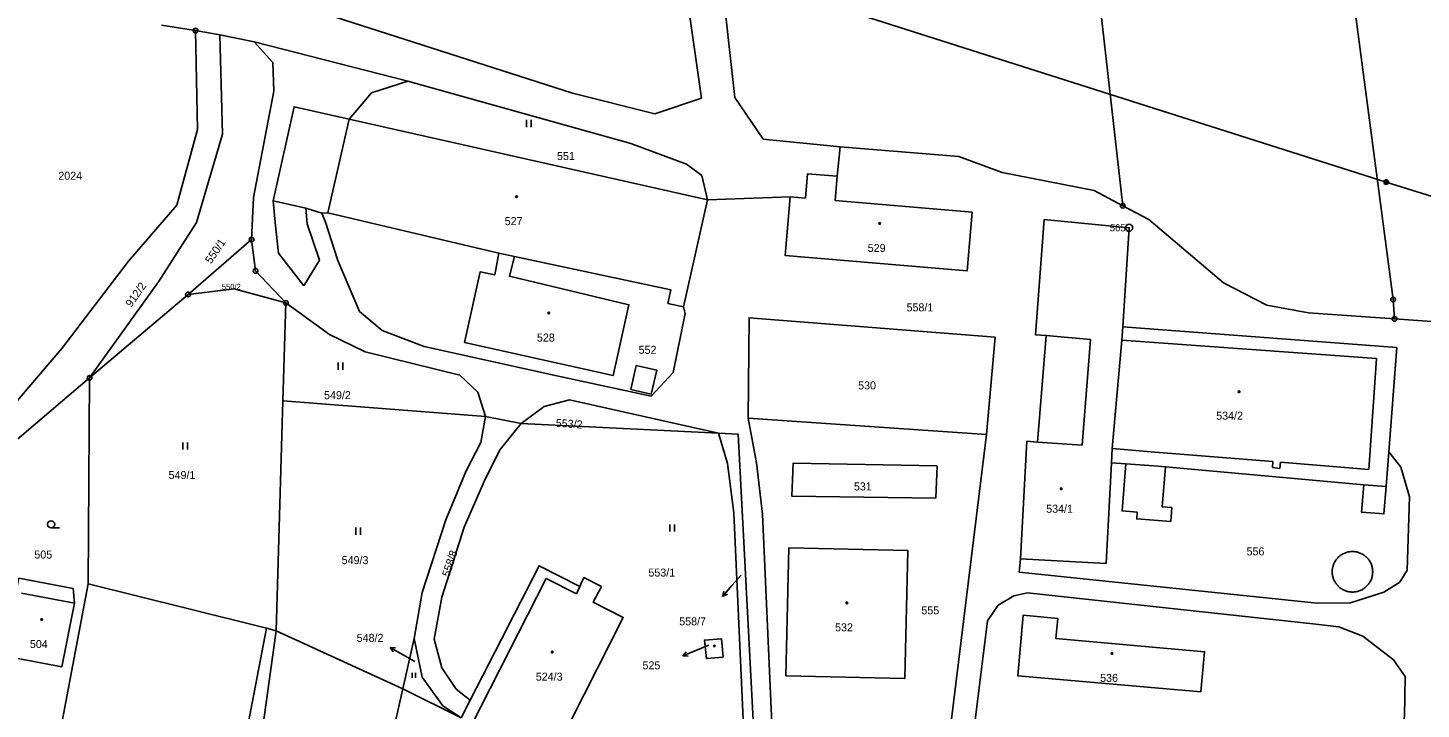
# Model space of a CAD drawing. Extents: x -504988 to -494607, y -1123820 to -1114018.
# Drawn here: x -499771.3 to -499475.3, y -1121291.8 to -1121147.2 of the extents above; entities that cross this region are included whole.
import ezdxf

# ---------------------------------------------------------------- set-up
doc = ezdxf.new("R2010")
doc.units = 0
for name, color, linetype in [('Hranice parcel', 7, 'Continuous'), ('Parcelní čísla', 7, 'Continuous'), ('Pop  PČ popisy', 7, 'Continuous'), ('Poz předměty', 7, 'Continuous'), ('Vnitřní kresba', 7, 'Continuous'), ('Značky bodu BP', 7, 'Continuous'), ('Značky budov', 7, 'Continuous'), ('Značky kultur', 7, 'Continuous')]:
    doc.layers.add(name, color=color, linetype=linetype)

msp = doc.modelspace()

# ---------------------------------------------------------------- linework, layer by layer
at = {"layer": 'Hranice parcel'}
for p, q in [((-499742.85, -1121146.58), (-499735.62, -1121147.76)), ((-499730.48, -1121148.62), (-499735.62, -1121147.76)), ((-499723.21, -1121150.1), (-499730.48, -1121148.62)), ((-499723.21, -1121150.1), (-499690.55, -1121158.46)), ((-499626.88, -1121183.66), (-499703.04, -1121166.56)), ((-499599.32, -1121178.67), (-499598.7, -1121172.43)), ((-499626.88, -1121183.66), (-499609.35, -1121183.04)), ((-499632, -1121206.43), (-499626.88, -1121183.66)), ((-499737.24, -1121203.77), (-499723.72, -1121192.13)), ((-499671.18, -1121195.02), (-499667.9, -1121195.75)), ((-499758.14, -1121221.5), (-499737.24, -1121203.77)), ((-499717.12, -1121226.36), (-499716.43, -1121205.57)), ((-499499.24, -1121207.68), (-499480.94, -1121208.98)), ((-499758.14, -1121221.5), (-499774.43, -1121235.32)), ((-499758.14, -1121221.5), (-499758.45, -1121265.23)), ((-499718.5, -1121275.17), (-499717.12, -1121226.36)), ((-499717.12, -1121226.36), (-499674.05, -1121229.68)), ((-499666.49, -1121231.16), (-499674.05, -1121229.68)), ((-499618.28, -1121230.05), (-499567.62, -1121233.51)), ((-499624.55, -1121233.22), (-499666.49, -1121231.16)), ((-499724.89, -1121297.16), (-499720.54, -1121274.67)), ((-499718.5, -1121275.17), (-499720.54, -1121274.67)), ((-499718.5, -1121275.17), (-499691.64, -1121287.55)), ((-499689.23, -1121276.84), (-499691.64, -1121287.55)), ((-499679.21, -1121293.69), (-499691.64, -1121287.55)), ((-499679.21, -1121293.69), (-499677.32, -1121289.95))]:
    msp.add_line(p, q, dxfattribs=at)
for points in [[(-499722.3, -1121143.47), (-499711.61, -1121143.06), (-499655.54, -1121161.04), (-499638.1, -1121165.41), (-499628.17, -1121162.11), (-499636.17, -1121106.02), (-499642.87, -1121066.62), (-499646.88, -1121045.2)], [(-499598.7, -1121172.43), (-499615.06, -1121170.79), (-499621.06, -1121161.96), (-499627.39, -1121105.08), (-499634.8, -1121065.28), (-499638.31, -1121046.8)], [(-499554.62, -1121062.41), (-499546.23, -1121118.09), (-499538.66, -1121184.94)], [(-499480.94, -1121208.98), (-499481.24, -1121204.85), (-499489.09, -1121145.31), (-499501.25, -1121074.72), (-499501.77, -1121072.27)], [(-499735.62, -1121147.76), (-499735.23, -1121168.72), (-499739.59, -1121184.85), (-499749.86, -1121196.74), (-499764.05, -1121215.27), (-499775.18, -1121228.26)], [(-499730.48, -1121148.62), (-499729.89, -1121169.75), (-499735.45, -1121188.47), (-499743.52, -1121201.09), (-499758.14, -1121221.5)], [(-499723.72, -1121192.13), (-499723.33, -1121183.19), (-499719.03, -1121160.6), (-499719.22, -1121154.49), (-499723.21, -1121150.1)], [(-499690.55, -1121158.46), (-499698.25, -1121160.95), (-499703.04, -1121166.56)], [(-499626.88, -1121183.66), (-499628.06, -1121178.54), (-499631.38, -1121176.11), (-499643.16, -1121171.74), (-499690.55, -1121158.46)], [(-499703.04, -1121166.56), (-499714.7, -1121163.91), (-499719.17, -1121183.93), (-499712.22, -1121185.47), (-499708.81, -1121186.5)], [(-499598.7, -1121172.43), (-499573.53, -1121174.51), (-499564.31, -1121177.87), (-499544.74, -1121181.71), (-499538.66, -1121184.94)], [(-499609.35, -1121183.04), (-499610.4, -1121195.48), (-499571.72, -1121198.74), (-499570.67, -1121186.3), (-499599.76, -1121183.85), (-499599.32, -1121178.67)], [(-499599.32, -1121178.67), (-499605.64, -1121178.14), (-499606.07, -1121183.32), (-499609.35, -1121183.04)], [(-499538.66, -1121184.94), (-499533.11, -1121187.89), (-499517.28, -1121201.31), (-499508.05, -1121206.07), (-499499.24, -1121207.68)], [(-499708.81, -1121186.5), (-499707.51, -1121186.46), (-499671.18, -1121195.02)], [(-499708.81, -1121186.5), (-499708.06, -1121188.46), (-499705.38, -1121196.55), (-499700.82, -1121207.36), (-499695.99, -1121211.43), (-499687.05, -1121214.82), (-499658.23, -1121221.22), (-499638.82, -1121225.39), (-499634.15, -1121220.36), (-499631.66, -1121207.8), (-499632, -1121206.43)], [(-499560.39, -1121259.88), (-499559.03, -1121234.96), (-499556.77, -1121235.15), (-499554.95, -1121212.51), (-499557.18, -1121212.37), (-499555.34, -1121187.89), (-499537.33, -1121189.62), (-499538.68, -1121210.68)], [(-499716.43, -1121205.57), (-499722.89, -1121198.76), (-499723.72, -1121192.13)], [(-499671.18, -1121195.02), (-499672.08, -1121199.63), (-499675.15, -1121198.95), (-499678.49, -1121213.98), (-499646.92, -1121221), (-499643.57, -1121205.97), (-499668.97, -1121199.92), (-499667.9, -1121195.75)], [(-499667.9, -1121195.75), (-499634.67, -1121202.81), (-499635.31, -1121205.68), (-499632, -1121206.43)], [(-499737.24, -1121203.77), (-499727.4, -1121202.59), (-499716.43, -1121205.57)], [(-499674.05, -1121229.68), (-499675.68, -1121224.55), (-499679.53, -1121220.94), (-499699.59, -1121215.95), (-499707.18, -1121212.31), (-499716.43, -1121205.57)], [(-499567.62, -1121233.51), (-499565.81, -1121212.87), (-499618.07, -1121208.74), (-499618.28, -1121230.05)], [(-499480.94, -1121208.98), (-499472, -1121209.62), (-499440.51, -1121211.63)], [(-499541.06, -1121239.56), (-499540.89, -1121236.51), (-499538.86, -1121213.5), (-499538.68, -1121210.68)], [(-499482.15, -1121237.17), (-499480.49, -1121215.04), (-499538.68, -1121210.68)], [(-499624.55, -1121233.22), (-499656.21, -1121226.16), (-499661.56, -1121227.54), (-499666.49, -1121231.16)], [(-499674.05, -1121229.68), (-499675.04, -1121235.19), (-499678.16, -1121241.24), (-499682.49, -1121251.62), (-499687.51, -1121267.04), (-499689.23, -1121276.84)], [(-499618.28, -1121230.05), (-499616.51, -1121239.55), (-499615.21, -1121250.4), (-499612.69, -1121306), (-499607.63, -1121311.95), (-499585.22, -1121315.4), (-499580.65, -1121312.61), (-499576.84, -1121308.33), (-499567.62, -1121233.51)], [(-499666.49, -1121231.16), (-499670.9, -1121236.72), (-499674.14, -1121242.98), (-499678.55, -1121253.22), (-499683.33, -1121268.05), (-499684.97, -1121276.97), (-499683.34, -1121283.06), (-499680.26, -1121287.6), (-499677.32, -1121289.95)], [(-499627.36, -1121310.43), (-499621.98, -1121308.54), (-499618.81, -1121305.01), (-499621.32, -1121250.12), (-499622.64, -1121239.66), (-499624.55, -1121233.22)], [(-499624.55, -1121233.22), (-499620.4, -1121233.46), (-499616.25, -1121311.73)], [(-499560.39, -1121259.88), (-499560.71, -1121262.72), (-499497.4, -1121269.35), (-499490.27, -1121269.24), (-499483.23, -1121266.97), (-499479.82, -1121264.88), (-499478.23, -1121262.3), (-499477.76, -1121246.78), (-499479.63, -1121240.44), (-499482.15, -1121237.17)], [(-499541.06, -1121239.56), (-499538.01, -1121239.75), (-499538.82, -1121249.75), (-499535.58, -1121250.01), (-499535.69, -1121251.43), (-499528.49, -1121251.97), (-499528.26, -1121249.02), (-499530.28, -1121248.86), (-499529.59, -1121240.39), (-499487.5, -1121244.17), (-499487.99, -1121249.98), (-499483.21, -1121250.36), (-499482.71, -1121244.54), (-499482.15, -1121237.17)], [(-499578.35, -1121247.06), (-499578.12, -1121240.17), (-499608.66, -1121239.58), (-499608.96, -1121246.61), (-499578.35, -1121247.06)], [(-499560.39, -1121259.88), (-499542.22, -1121260.9), (-499541.06, -1121239.56)], [(-499584.96, -1121285.36), (-499584.3, -1121258.17), (-499609.59, -1121257.57), (-499610.24, -1121284.75), (-499584.96, -1121285.36)], [(-499658.64, -1121299.61), (-499644.8, -1121272.34), (-499651.14, -1121269.15), (-499649.42, -1121265.81), (-499653.19, -1121263.9), (-499654, -1121265.77), (-499662.66, -1121261.39), (-499677.32, -1121289.95)], [(-499775.2, -1121280.69), (-499764.01, -1121282.84), (-499761.38, -1121269.32), (-499761.6, -1121266.24), (-499773.15, -1121264.04), (-499776.76, -1121280.41), (-499775.2, -1121280.69)], [(-499768.83, -1121319.89), (-499768.42, -1121317.94), (-499758.45, -1121265.23)], [(-499720.54, -1121274.67), (-499737.38, -1121270.46), (-499758.45, -1121265.23)], [(-499486.87, -1121324.22), (-499486.86, -1121323.39), (-499479.81, -1121298.97), (-499478.82, -1121293.36), (-499478.67, -1121284.88), (-499481.16, -1121281.36), (-499487.7, -1121276.33), (-499492.76, -1121274.33), (-499497.63, -1121273.78), (-499558.94, -1121267.14), (-499561.8, -1121267.75), (-499565.13, -1121269.75), (-499567.38, -1121273.1), (-499570.95, -1121301.52)], [(-499522.06, -1121288.16), (-499521.31, -1121279.63), (-499552.88, -1121276.86), (-499552.5, -1121272.55), (-499559.85, -1121271.9), (-499560.97, -1121284.74), (-499522.06, -1121288.16)], [(-499721.37, -1121318.52), (-499723.64, -1121312.8), (-499722.48, -1121303.72), (-499718.5, -1121275.17)], [(-499689.23, -1121276.84), (-499687.48, -1121285.03), (-499683.09, -1121291.14), (-499679.21, -1121293.69)], [(-499623.91, -1121276.89), (-499627.53, -1121277.15), (-499627.13, -1121281.11), (-499623.58, -1121280.82), (-499623.91, -1121276.89)], [(-499691.64, -1121287.55), (-499697.61, -1121314.02), (-499705.71, -1121331.61)]]:
    msp.add_lwpolyline(points, dxfattribs=at)
at = {"layer": 'Pop  PČ popisy'}
for p, q in [((-499621.72, -1121265.61), (-499623.69, -1121267.88)), ((-499619.75, -1121263.36), (-499621.72, -1121265.61)), ((-499623.69, -1121267.88), (-499623.41, -1121266.79)), ((-499623.69, -1121267.88), (-499622.65, -1121267.45)), ((-499691.68, -1121280.23), (-499694.28, -1121278.73)), ((-499694.28, -1121278.73), (-499693.16, -1121278.8)), ((-499694.28, -1121278.73), (-499693.66, -1121279.66)), ((-499689.09, -1121281.74), (-499691.68, -1121280.23)), ((-499629.35, -1121279.39), (-499632.13, -1121280.51)), ((-499632.13, -1121280.51), (-499631.39, -1121279.68)), ((-499632.13, -1121280.51), (-499631.02, -1121280.6)), ((-499626.57, -1121278.27), (-499629.35, -1121279.39))]:
    msp.add_line(p, q, dxfattribs=at)
at = {"layer": 'Poz předměty'}
for p, q in [((-499632.39, -1121132.32), (-499482.71, -1121179.91)), ((-499482.71, -1121179.91), (-499339.41, -1121225.24))]:
    msp.add_line(p, q, dxfattribs=at)
for radius in [0.5, 0.4, 0.3, 0.2, 0.1]:
    msp.add_circle((-499482.71, -1121179.91), radius, dxfattribs=at)
at = {"layer": 'Vnitřní kresba'}
for p, q in [((-499707.51, -1121186.46), (-499703.04, -1121166.56)), ((-499718.66, -1121189.23), (-499719.17, -1121183.93)), ((-499712.22, -1121185.47), (-499711.96, -1121188.78)), ((-499711.96, -1121188.78), (-499709.32, -1121196.51)), ((-499718.04, -1121195.04), (-499718.66, -1121189.23)), ((-499712.61, -1121201.98), (-499718.04, -1121195.04)), ((-499709.32, -1121196.51), (-499712.61, -1121201.98)), ((-499554.95, -1121212.51), (-499545.54, -1121213.33)), ((-499545.54, -1121213.33), (-499547.29, -1121235.78)), ((-499538.86, -1121213.5), (-499484.74, -1121217.38)), ((-499484.74, -1121217.38), (-499486.43, -1121240.92)), ((-499643.16, -1121223.98), (-499642.01, -1121218.89)), ((-499642.01, -1121218.89), (-499637.67, -1121219.87)), ((-499637.67, -1121219.87), (-499638.82, -1121224.96)), ((-499638.82, -1121224.96), (-499643.16, -1121223.98)), ((-499547.29, -1121235.78), (-499556.77, -1121235.15)), ((-499538.41, -1121236.71), (-499540.89, -1121236.51)), ((-499531.85, -1121237.25), (-499538.41, -1121236.71)), ((-499506.78, -1121239.28), (-499531.85, -1121237.25)), ((-499506.88, -1121240.55), (-499506.78, -1121239.28)), ((-499505.18, -1121239.41), (-499505.29, -1121240.7)), ((-499486.43, -1121240.92), (-499505.18, -1121239.41)), ((-499532.09, -1121240.19), (-499538.01, -1121239.75)), ((-499529.59, -1121240.39), (-499532.09, -1121240.19)), ((-499505.29, -1121240.7), (-499506.88, -1121240.55)), ((-499487.5, -1121244.17), (-499482.71, -1121244.54)), ((-499677.02, -1121295.24), (-499661.15, -1121264.12)), ((-499661.15, -1121264.12), (-499654.69, -1121267.37)), ((-499654.69, -1121267.37), (-499654, -1121265.77)), ((-499772.61, -1121267.21), (-499761.38, -1121269.32))]:
    msp.add_line(p, q, dxfattribs=at)
for points in [[(-499489.88, -1121258.36), (-499490.07, -1121258.36), (-499490.25, -1121258.38), (-499490.43, -1121258.4), (-499490.62, -1121258.42), (-499490.8, -1121258.46), (-499490.98, -1121258.5), (-499491.16, -1121258.55), (-499491.33, -1121258.61), (-499491.5, -1121258.68), (-499491.67, -1121258.75), (-499491.84, -1121258.83), (-499492, -1121258.92), (-499492.16, -1121259.02), (-499492.32, -1121259.12), (-499492.47, -1121259.23), (-499492.61, -1121259.34), (-499492.75, -1121259.46), (-499492.89, -1121259.59), (-499493.02, -1121259.72), (-499493.14, -1121259.86), (-499493.26, -1121260), (-499493.37, -1121260.15), (-499493.47, -1121260.3), (-499493.57, -1121260.46), (-499493.66, -1121260.62), (-499493.75, -1121260.78), (-499493.83, -1121260.95), (-499493.9, -1121261.12), (-499493.96, -1121261.3), (-499494.01, -1121261.47), (-499494.06, -1121261.65), (-499494.1, -1121261.83), (-499494.13, -1121262.02), (-499494.16, -1121262.2), (-499494.17, -1121262.38), (-499494.18, -1121262.57), (-499494.18, -1121262.75), (-499494.17, -1121262.94), (-499494.16, -1121263.12), (-499494.13, -1121263.3), (-499494.1, -1121263.49), (-499494.06, -1121263.67), (-499494.01, -1121263.85), (-499493.96, -1121264.02), (-499493.9, -1121264.2), (-499493.83, -1121264.37), (-499493.75, -1121264.54), (-499493.66, -1121264.7), (-499493.57, -1121264.86), (-499493.47, -1121265.02), (-499493.37, -1121265.17), (-499493.26, -1121265.32), (-499493.14, -1121265.46), (-499493.02, -1121265.6), (-499492.89, -1121265.73), (-499492.75, -1121265.86), (-499492.61, -1121265.98), (-499492.47, -1121266.09), (-499492.32, -1121266.2), (-499492.16, -1121266.3), (-499492, -1121266.4), (-499491.84, -1121266.49), (-499491.67, -1121266.57), (-499491.5, -1121266.64), (-499491.33, -1121266.71), (-499491.16, -1121266.77), (-499490.98, -1121266.82), (-499490.8, -1121266.86), (-499490.62, -1121266.9), (-499490.43, -1121266.92), (-499490.25, -1121266.94), (-499490.07, -1121266.96), (-499489.88, -1121266.96), (-499489.7, -1121266.96), (-499489.51, -1121266.94), (-499489.33, -1121266.92), (-499489.14, -1121266.9), (-499488.96, -1121266.86), (-499488.78, -1121266.82), (-499488.6, -1121266.77), (-499488.43, -1121266.71), (-499488.26, -1121266.64), (-499488.09, -1121266.57), (-499487.92, -1121266.49), (-499487.76, -1121266.4), (-499487.6, -1121266.3), (-499487.44, -1121266.2), (-499487.29, -1121266.09), (-499487.15, -1121265.98), (-499487.01, -1121265.86), (-499486.87, -1121265.73), (-499486.74, -1121265.6), (-499486.62, -1121265.46), (-499486.5, -1121265.32), (-499486.39, -1121265.17), (-499486.29, -1121265.02), (-499486.19, -1121264.86), (-499486.1, -1121264.7), (-499486.01, -1121264.54), (-499485.93, -1121264.37)], [(-499485.93, -1121264.37), (-499485.86, -1121264.2), (-499485.8, -1121264.02), (-499485.75, -1121263.85), (-499485.7, -1121263.67), (-499485.66, -1121263.49), (-499485.63, -1121263.3), (-499485.6, -1121263.12), (-499485.59, -1121262.94), (-499485.58, -1121262.75), (-499485.58, -1121262.57), (-499485.59, -1121262.38), (-499485.6, -1121262.2), (-499485.63, -1121262.02), (-499485.66, -1121261.83), (-499485.7, -1121261.65), (-499485.75, -1121261.47), (-499485.8, -1121261.3), (-499485.86, -1121261.12), (-499485.93, -1121260.95), (-499486.01, -1121260.78), (-499486.1, -1121260.62), (-499486.19, -1121260.46), (-499486.29, -1121260.3), (-499486.39, -1121260.15), (-499486.5, -1121260), (-499486.62, -1121259.86), (-499486.74, -1121259.72), (-499486.87, -1121259.59), (-499487.01, -1121259.46), (-499487.15, -1121259.34), (-499487.29, -1121259.23), (-499487.44, -1121259.12), (-499487.6, -1121259.02), (-499487.76, -1121258.92), (-499487.92, -1121258.83), (-499488.09, -1121258.75), (-499488.26, -1121258.68), (-499488.43, -1121258.61), (-499488.6, -1121258.55), (-499488.78, -1121258.5), (-499488.96, -1121258.46), (-499489.14, -1121258.42), (-499489.33, -1121258.4), (-499489.51, -1121258.38), (-499489.7, -1121258.36), (-499489.88, -1121258.36)]]:
    msp.add_lwpolyline(points, dxfattribs=at)
at = {"layer": 'Značky bodu BP'}
for centre, radius in [((-499735.62, -1121147.76), 0.5), ((-499735.62, -1121147.76), 0.0303), ((-499538.66, -1121184.94), 0.5), ((-499538.66, -1121184.94), 0.0303), ((-499537.33, -1121189.62), 0.75), ((-499723.72, -1121192.13), 0.5), ((-499537.33, -1121189.62), 0.03), ((-499723.72, -1121192.13), 0.0303), ((-499722.89, -1121198.76), 0.5), ((-499722.89, -1121198.76), 0.0303), ((-499737.24, -1121203.77), 0.5), ((-499737.24, -1121203.77), 0.0303), ((-499716.43, -1121205.57), 0.5), ((-499716.43, -1121205.57), 0.0303), ((-499481.24, -1121204.85), 0.5), ((-499481.24, -1121204.85), 0.0303), ((-499480.94, -1121208.98), 0.5), ((-499480.94, -1121208.98), 0.0303), ((-499758.14, -1121221.5), 0.5), ((-499758.14, -1121221.5), 0.0303)]:
    msp.add_circle(centre, radius, dxfattribs=at)
at = {"layer": 'Značky budov'}
for centre in [(-499667.45, -1121183), (-499590.33, -1121188.7), (-499660.6, -1121207.73), (-499513.96, -1121224.45), (-499551.75, -1121245.04), (-499597.28, -1121269.26), (-499768.31, -1121272.81), (-499659.87, -1121279.73), (-499625.44, -1121278.43), (-499540.96, -1121280)]:
    msp.add_circle(centre, 0.175, dxfattribs=at)
at = {"layer": 'Značky kultur'}
for p, q in [((-499665.31, -1121168.23), (-499665.31, -1121166.73)), ((-499664.31, -1121168.23), (-499664.31, -1121166.73)), ((-499705.35, -1121219.76), (-499705.35, -1121218.26)), ((-499704.35, -1121219.76), (-499704.35, -1121218.26)), ((-499738.37, -1121236.72), (-499738.37, -1121235.22)), ((-499737.37, -1121236.72), (-499737.37, -1121235.22)), ((-499766.31, -1121253.33), (-499764.56, -1121253.33)), ((-499701.61, -1121254.79), (-499701.61, -1121253.29)), ((-499700.61, -1121254.79), (-499700.61, -1121253.29)), ((-499634.91, -1121254.09), (-499634.91, -1121252.59)), ((-499633.91, -1121254.09), (-499633.91, -1121252.59)), ((-499689.59, -1121285.2), (-499689.59, -1121284.15)), ((-499688.89, -1121285.2), (-499688.89, -1121284.15))]:
    msp.add_line(p, q, dxfattribs=at)
msp.add_circle((-499766.31, -1121252.58), 0.75, dxfattribs=at)

# ---------------------------------------------------------------- texts
at = {"layer": 'Parcelní čísla'}
for s, height, p in [('551', 1.7, (-499658.86, -1121175.23)), ('2024', 1.7, (-499764.78, -1121179.41)), ('527', 1.7, (-499669.97, -1121189.05)), ('529', 1.7, (-499592.85, -1121194.75)), ('550/2', 1.2, (-499730.05, -1121202.73)), ('558/1', 1.7, (-499584.6, -1121207.37)), ('528', 1.7, (-499663.12, -1121213.78)), ('552', 1.7, (-499641.52, -1121216.38)), ('549/2', 1.7, (-499708.34, -1121226.01)), ('530', 1.7, (-499594.89, -1121223.94)), ('534/2', 1.7, (-499518.83, -1121230.37)), ('549/1', 1.7, (-499741.36, -1121242.97)), ('531', 1.7, (-499595.79, -1121245.39)), ('534/1', 1.7, (-499554.94, -1121250.13)), ('505', 1.7, (-499769.88, -1121259.86)), ('549/3', 1.7, (-499704.6, -1121261.04)), ('556', 1.7, (-499512.38, -1121259.18)), ('553/1', 1.7, (-499639.44, -1121263.68)), ('555', 1.7, (-499581.46, -1121271.7)), ('558/7', 1.7, (-499632.9, -1121274.04)), ('532', 1.7, (-499599.79, -1121275.31)), ('504', 1.7, (-499770.83, -1121278.86)), ('548/2', 1.7, (-499701.41, -1121277.55)), ('525', 1.7, (-499640.7, -1121283.38)), ('524/3', 1.7, (-499663.36, -1121285.78)), ('536', 1.7, (-499543.48, -1121286.05))]:
    msp.add_text(s, height=height, dxfattribs=at).set_placement(p)
for s, rotation, p in [('550/1', 56, (-499732.33, -1121197.4)), ('912/2', 55, (-499749.27, -1121206.61)), ('553/2', 356, (-499659.17, -1121231.87)), ('558/8', 72, (-499681.72, -1121263.86))]:
    msp.add_text(s, height=1.7, rotation=rotation, dxfattribs=at).set_placement(p)
at = {"layer": 'Značky bodu BP'}
msp.add_text('565', height=1.5, dxfattribs=at).set_placement((-499541.43, -1121190.37))

doc.saveas('drawing.dxf')
